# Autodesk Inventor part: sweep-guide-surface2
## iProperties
Created: 2006-01
Part Number: sweep-guide-surface2
Document SubType Name: Modeling
Designer: CADCIM
Author: CADCIM
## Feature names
1. Extrusion1
2. Sweep1
